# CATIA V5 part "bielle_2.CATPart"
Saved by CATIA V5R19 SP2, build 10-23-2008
Part number: bielle_2
Bounding box of the stored display mesh (mm): x 10 to 20, y -7.997 to 7.997, z -7.99 to 92.99
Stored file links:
  D:\Dropbox\IAO_2011\MMS_GR2\IAO_2011_1492_afeiguel\IAO_2011_1492_afeiguel\bielle_2.CATPart
  C:\Users\Nono\Desktop\projets ifma\IAO finis\assemblage_IAO.CATProduct
  D:\Dropbox\IAO_2011\MMS_GR2\IAO_2011_1492_afeiguel\IAO_2011_1492_afeiguel\coulisseau_3.CATPart
  D:\Dropbox\IAO_2011\MMS_GR2\IAO_2011_1492_afeiguel\IAO_2011_1492_afeiguel\bielle_1.CATPart
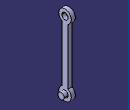
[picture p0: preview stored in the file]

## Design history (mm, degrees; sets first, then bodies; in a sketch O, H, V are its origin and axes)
Parameters
  BC = 85 mm
  r_tetebielle = 8 mm
  e_bielle = 5 mm
Set1
  DatumSurface1: linked copy from another document
  DatumPoint1: linked copy from another document
Body1 (main body)
  Sketch1 on yz-plane, origin (0, 0, 0), H (0, 1, 0), V (0, 0, 1)
    point P1 (0, 0)
    point P2 (0, 85)
    line L1 (0, 0) -> (0, 85)
    distance P2 O = 85 {= BC}
    coincidence: P1 O, P2 V
    vertical: L1 V
  Sketch2 on zx-plane, origin (0, 0, 0), H (-1, 0, 0), V (0, 0, 1)
    line L1 (-49.8432, 0) -> (44.8141, 0)
    point P1 (-49.8432, 0)
    line L2 (-49.8432, 85) -> (44.8141, 85)
    reference projected point E1 (0, 85) from Sketch1.P2
    distance L2 E1 = 0
    coincidence: P1 H
    horizontal: L1 H, L2 H
  Sketch3 on face of DatumSurface1, origin (10, 0, 0), H (0, 1, 0), V (0, 0, 1)
    arc A1 centre (0, 85) radius 8 from (3.873, 78) to (-3.873, 78) ccw
    point P1 (0, 85)
    reference projected point E1 (0, 85) from Sketch1.P2
    arc A2 centre (0, 0) radius 8 from (-3.873, 7) to (3.873, 7) ccw
    point P4 (-3.873, 7)
    point P5 (3.873, 7)
    line L1 (-3.873, 7) -> (-3.873, 78)
    line L2 (3.873, 7) -> (3.873, 78)
    point P6 (3.873, -15)
    circle A3 centre (0, 85) radius 4
    point P7 (4, 0)
    radius A2 = 8 {= r_tetebielle}
    distance P1 A1 = 8 {= r_tetebielle}
    distance H P5 = 7 {= r_tetebielle -1mm}
    distance P4 H = 7 {= Sketch3.distance(H P5)}
    distance A3 P1 = 4 {= Sketch3.radius(A2) -4mm}
    coincidence: P1 V, E1 P1, P6 L2, P7 H
  Pad1: profile Sketch3, direction (1, 0, 0), length 5
  Sketch4 on end face of Pad1, origin (15, 0, 0), H (0, 1, 0), V (0, 0, 1)
    circle A1 centre (0, 0) radius 4
    distance A1 O = 4 {= r_tetebielle-4mm}
  Pad2: profile Sketch4, direction (1, 0, 0), length 5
